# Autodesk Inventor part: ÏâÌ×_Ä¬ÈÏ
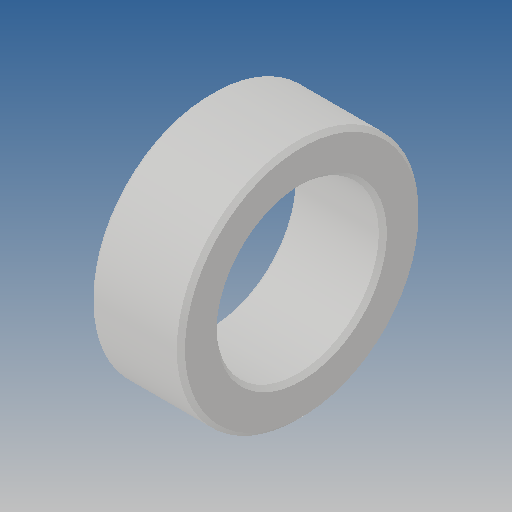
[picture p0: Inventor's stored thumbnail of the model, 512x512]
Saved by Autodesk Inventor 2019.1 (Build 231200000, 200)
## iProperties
Created: 2012-10
Part Number: ÏâÌ×_Ä¬ÈÏ
Material: Ogólny
Document SubType Name: Modeling
Designer: CADENGINEERING4
Density: 1 g/cm^3
Appearance: Domyślna
Author: CADENGINEERING4
Revision Number: ÈÎºÎ
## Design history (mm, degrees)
feature "NONE"
node "Bryła1"
